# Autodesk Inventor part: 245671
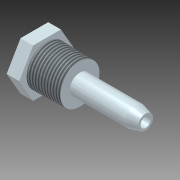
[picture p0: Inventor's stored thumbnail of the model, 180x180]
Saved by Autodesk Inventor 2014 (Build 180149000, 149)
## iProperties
Shininess: 20.0
Length Units: 11272
Angle Units: 11279
Time Units: 11290
Mass Units: 11286
Length Display Precision: 3
Angle Display Precision: 2
Company: Autodesk, Inc.
Created: 2002-07
Part Number: 245671
Material: Stainless Steel 316
Description: THERMOWELL
Document SubType Name: Modeling
Designer: Autodesk, Inc.
Density: 8.182 g/cm^3
Mass: 100.571 g
Surface Area: 79.2351 cm^2
Volume: 12.2917 cm^3
Appearance: Stainless Steel
Density: 0.0
Volumn: 0.0
Area: 0.0
PropertySet Name: Model Information
Control State: 0
Master: False
Checked Out: False
Last Check In By: JT
Last Check In Date: 2003-06-20
Title: THERMOWELL
Author: Autodesk, Inc.
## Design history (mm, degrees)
sketch "Sketch1"
  geometry: L1 (0, 0)-(59.434, 0); L2 (17.463, 3.175)-(61.913, 3.175); L3 (61.913, 3.175)-(61.913, 4.649); L4 (61.913, 4.649)-(55.563, 6.35); L5 (55.563, 6.35)-(20.638, 6.35); L6 (20.638, 6.35)-(20.638, 12.29); L7 (20.638, 12.29)-(0, 12.785); L8 (0, 12.785)-(0, 14.979); L9 (0, 14.979)-(-7.938, 14.979); L10 (-7.938, 14.979)-(-7.937, 10.113); L11 (17.463, 3.175)-(17.463, 9.632); L12 (17.463, 9.632)-(-7.937, 10.113)
  constraints: 24 end point, 7 parallel, 1 horizontal, 1 perpendicular, 1 vertical alignment
  dimensions: "d3" = 6.35 diameter of L2 L1; "d4" = 12.7 diameter of L5 L1; "d5" = 41.275 distance between parallel lines of L6 L3; "d6" = 6.35 horizontal distance of L3.end L4.end; "d7" = 15 deg angle of L5 L4; "d8" = 20.6375 distance between parallel lines of L6 L8; "d9" = 7.9375 distance of L8.end L9.end; "d10" = 3.175 distance between parallel lines of L11 L6; "d11" = 29.95743 diameter of L9 L1; "d12" = 24.57907 diameter of L6.end L1; "d13" = 25.57018 diameter of L7.end L1; "d14" = 19.26412 diameter of L11.end L1; "d15" = 20.22602 diameter of L10.end L1
revolve "Revolution1" sketch "Sketch1" stored, may be unused: angle "d16" = 90 deg
thread "Thread1" dims "d17" = 25.4, "d18" = 0
thread "Thread2" dims "d19" = 25.4, "d20" = 0
sketch "Sketch2"
  geometry: L1 (-8.707, -15.081)-(-17.414, 0); L2 (-17.414, 0)-(-8.707, 15.081); L3 (-8.707, 15.081)-(8.707, 15.081); L4 (8.707, 15.081)-(17.414, 0); L5 (17.414, 0)-(8.707, -15.081); L6 (8.707, -15.081)-(-8.707, -15.081); C1 r 14.979 at (0, 0) reference; C2 r 10.113 at (0, 0) reference; 1 further point
  constraints: 12 end point, 1 coincident, 1 horizontal, 11 other
  dimensions: "d21" = 30.1625 distance between parallel lines of L5 L2
extrude "Extrusion2" join sketch "Sketch2" stored distance "d22" = 25.4; taper "d23" = 0 deg
body "Solid1"
